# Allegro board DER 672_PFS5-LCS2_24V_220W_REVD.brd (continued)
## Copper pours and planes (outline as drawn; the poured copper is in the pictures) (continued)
N4398139 on TOP: 147.15,73.13 147.15,62.68 147.39,62.43 153.55,62.43 153.98,62.87 153.98,67.92 155.45,69.39 156.78,70.71 156.78,74.45 156.17,75.06 149.08,75.06
N4398139 on BOTTOM: 147.15,62.93 147.15,73.15 149.06,75.06 156.17,75.06 156.79,74.43 156.79,70.73 153.98,67.92 153.98,63.03 153.71,62.76 147.31,62.76
N4399978 on BOTTOM (solid shape): 153.9,46.53 149.87,46.53 149.87,50.75 153.9,50.75
N4399978 on TOP: 149.33,58.95 148.37,57.99 148.37,46.76 149.52,45.61 153.57,45.61 154.01,46.05 154.01,51.33 154.72,52.04 154.74,52.04 155.78,53.08 155.78,57.93 154.76,58.95 154.54,58.95 154.54,58.95 154.24,58.95
N4399978 on BOTTOM: 149.01,46.12 148.37,46.76 148.37,57.99 149.33,58.95 154.76,58.95 155.78,57.93 155.78,53.11 154.01,51.33 154.01,46.25 153.88,46.12
N4403558 on BOTTOM: 155.81,63.59 154.96,63.59 154.96,62.67 154.41,62.13 154.02,62.13 154.01,62.14 153.21,62.14 153.21,61.2 153.23,61.18 155.8,61.18 155.8,63.58
N4433947 on BOTTOM: 155.85,46.93 155.04,46.93 155.02,46.92 155.02,46.17 154.31,45.46 154.31,45.47 153.53,45.47 153.53,44.51 153.53,44.5 155.45,44.5 155.84,44.5
N4535120 on BOTTOM: 117.99,24.56 117.71,24.28 116.07,24.28 116.07,25.59 115.3,26.36 115.3,27.76 114.97,28.09 113.47,28.09 113.04,28.52 113.04,29.03 115.08,29.03 115.3,29.25 116.47,29.25 116.6,29.12 116.6,27.86 117.99,26.47
N12141521 on TOP: 111.86,49.75 108.24,46.13 102.65,46.13 101.63,45.11 101.63,34.57 101.83,34.37 110.6,34.37 110.71,34.48 110.71,38.94 112,40.24 112,43.6 115.98,47.59 116.15,47.76 116.15,51.66 115.13,52.68 112.83,52.68 111.86,51.71
N12141521 on BOTTOM: 104.22,34.37 104.11,34.48 104.11,38.33 101.63,40.81 101.63,45.14 102.62,46.13 108.26,46.13 111.87,49.73 111.87,51.71 112.82,52.67 115.13,52.67 116.14,51.65 116.14,47.76 115.98,47.6 112,43.61 112,40.24 109.96,38.21 109.86,38.1 109.86,34.49 109.73,34.37
N12204254 on BOTTOM (solid shape): 10.34,46.37 9.84,47.37 9.34,46.37 8.84,47.37 8.34,46.37 8.34,49.37 10.34,49.37
N12204254 on BOTTOM (solid shape): 16.16,71.62 14.16,71.62 14.16,74.62 14.66,73.62 15.16,74.62 15.66,73.62 16.16,74.62
N12204254 on TOP: 7.66,55.35 7.66,56.08 5.93,57.81 5.93,63.98 10.12,68.17 13.8,68.17 13.93,68.3 13.93,69.44 14.59,70.1 15.71,70.1 16.39,69.42 16.39,66.42 15.96,65.99 11.72,65.99 8.85,63.12 8.85,59.36 11.11,57.1 11.11,55.37 10.2,54.46 8.54,54.46
N12204254 on BOTTOM: 7.66,49.17 7.66,56.08 5.93,57.81 5.93,63.98 10.12,68.17 13.8,68.17 13.93,68.3 13.93,72.39 14.11,72.57 16.16,72.57 16.39,72.34 16.39,66.42 15.96,65.99 11.72,65.99 8.85,63.12 8.85,59.36 11.11,57.1 11.11,49.25 10.35,48.49 8.34,48.49
N12204278 on BOTTOM (solid shape): 16.15,75.14 15.65,76.14 15.15,75.14 14.65,76.14 14.15,75.14 14.15,78.14 16.15,78.14
N12204278 on TOP: 36.25,67.74 24.04,79.96 14.59,79.96 13.93,80.62 13.93,81.71 14.77,82.55 25.64,82.55 37.4,70.79 39.76,70.79 40.65,69.9 40.65,68.66 39.74,67.74
N12204278 on BOTTOM: 36.25,67.74 24.04,79.96 16.57,79.96 16.39,79.78 16.39,77.47 16.14,77.22 14.16,77.22 13.93,77.44 13.93,81.71 14.77,82.55 25.64,82.55 37.4,70.79 39.76,70.79 40.65,69.9 40.65,68.66 39.74,67.74
N12204372 on TOP, BOTTOM: 45.46,65.19 40.93,60.65 38.18,60.65 37.2,59.67 37.2,51.18 38.01,50.37 42.68,50.37 43.57,51.26 43.57,60.43 48.37,65.22 48.37,68.76 47.6,69.52 46.47,69.52 45.68,68.74 45.68,65.41
N12204532 on BOTTOM (solid shape): 21.39,46.4 20.89,47.4 20.39,46.4 19.89,47.4 19.39,46.4 19.39,49.4 21.39,49.4
N12204532 on TOP: 18.65,55.4 18.65,61.55 19.82,62.71 19.85,62.71 22.84,65.71 39.77,65.71 40.65,64.83 40.65,63.55 39.76,62.66 24.54,62.66 22.11,60.22 22.11,56.36 22.11,56.36 22.11,55.37 21.14,54.41 19.64,54.41
N12204532 on BOTTOM: 18.66,49.22 18.66,51.49 18.65,51.49 18.65,61.55 19.82,62.71 19.85,62.71 22.84,65.71 39.77,65.71 40.65,64.83 40.65,63.55 39.76,62.66 24.54,62.66 22.11,60.22 22.11,56.36 22.11,56.36 22.11,49.22 21.37,48.49 19.39,48.49
N12221868 on TOP: 67.52,20.75 75.04,20.75 75.27,20.52 75.27,17.5 74.91,17.14 68.11,17.14 66.41,18.85 66.41,19.63
N12221868 on BOTTOM: 67.98,20.69 69.96,20.69 69.96,20.69 70,20.64 70,18.69 69.95,18.64 67.88,18.64 66.74,17.5 64.96,17.5 64.85,17.6 64.85,19.65 66.94,19.66
N12387180 on TOP: 12.86,3.56 11.34,5.08 7.71,5.08 6.51,6.27 5.13,6.27 4.61,5.73 4.61,4.37 8.59,0.38 11.59,0.38 12.86,1.65
N12387180 on BOTTOM: 12.86,3.56 11.34,5.08 7.71,5.08 6.51,6.27 5.14,6.27 4.61,5.73 4.61,4.39 8.59,0.41 11.59,0.41 12.86,1.68
N12387180 on BOTTOM: 12.86,3.56 11.34,5.08 7.71,5.08 6.51,6.27 5.14,6.27 4.61,5.73 4.61,4.37 8.59,0.38 11.59,0.38 12.86,1.65
N12539062 on TOP, BOTTOM: 130.77,21.21 130.03,20.47 128.08,20.47 127.34,19.74 126.1,19.74 125.49,20.34 125.49,21.46 126.17,22.15 128.1,22.15 128.76,22.81 130.11,22.81 130.77,22.15

Small or netless copper shapes (teardrops, artwork), in the pictures only: 1 on BOTTOM

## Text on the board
Ref Des/Silkscreen Bottom: TM | (A) | HiperLCS -SR | (C)
Ref Des/Silkscreen Top: S/N: | 2314 | DER 672 RevD | PFS5+LCS2_220W/24V | L | N | GND | +24V
PAGE_OUTLINE: PLATED | SLOT | UNPLATED SLOT
User.7: NOTES: PLEASE DELETE THESE PINS | 13. MATERIALFR4 COPPER 2oz THICKNESS 0.062"
User.9: FIGURE | FINISHED_SIZE | 18.0 | 20.0 | 30.0 | 35.0 | 40.0 | 50.0 | 52.012 | 60.0 | 67.012 | 70.0 | 80.0 | 100.0 | DRILL CHART: TOP to BOTTOM | ALL UNITS ARE IN MILS | TOLERANCE_DRILL | +3.0/-3.0 | +0.0/-0.0 | PLATED | QTY | 644 | 19 | 3 | 2 | 1 | 4 | 30 | 18 | 8 | 24 | 16 | 6
